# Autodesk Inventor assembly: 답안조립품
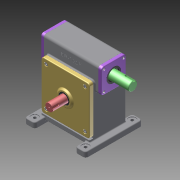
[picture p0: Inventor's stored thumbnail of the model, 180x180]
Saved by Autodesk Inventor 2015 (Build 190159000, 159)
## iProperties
Created: 2025-06
Part Number: 답안조립품
Document SubType Name: Assembly
Designer: User
Author: User
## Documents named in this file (13)
- C:\Users\User\Desktop\750603V1011\답안조립품.iam
- C:\Users\User\Documents\Inventor\6각 구멍붙이 볼트 M6x12.ipt
- C:\Users\User\Desktop\750603V1011\가져온 구성요소\6각 구멍붙이 볼트 M8x20\6각 구멍붙이 볼트 M8x20.ipt
- C:\Users\User\Desktop\750603V1011\가져온 구성요소\깊은 홈 볼 베어링 6206\깊은 홈 볼 베어링 6206.ipt
- C:\Users\User\Desktop\750603V1011\가져온 구성요소\깊은 홈 볼 베어링 6209\깊은 홈 볼 베어링 6209.ipt
- C:\Users\User\Desktop\750603V1011\가져온 구성요소\뒷커버\뒷커버.ipt
- C:\Users\User\Desktop\750603V1011\본체.ipt
- C:\Users\User\Desktop\750603V1011\가져온 구성요소\앞커버\앞커버.ipt
- C:\Users\User\Desktop\750603V1011\가져온 구성요소\오일 실 30 42 7\오일 실 30 42 7.ipt
- C:\Users\User\Desktop\750603V1011\가져온 구성요소\오일 실 35 55 11\오일 실 35 55 11.ipt
- C:\Users\User\Desktop\750603V1011\가져온 구성요소\웜 샤프트\웜 샤프트.ipt
- C:\Users\User\Desktop\750603V1011\가져온 구성요소\웜 휠 커버\웜 휠 커버.ipt
- C:\Users\User\Desktop\750603V1011\가져온 구성요소\웜 휠\웜 휠.ipt
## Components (12 placed, 2 different names)
1. 6각 구멍붙이 볼트 M8x20:1
2. 6각 구멍붙이 볼트 M8x20:2
3. 6각 구멍붙이 볼트 M8x20:3
4. 6각 구멍붙이 볼트 M8x20:4
5. 6각 구멍붙이 볼트 M6x12:1
6. 6각 구멍붙이 볼트 M6x12:3
7. 6각 구멍붙이 볼트 M6x12:4
8. 6각 구멍붙이 볼트 M6x12:5
9. 6각 구멍붙이 볼트 M6x12:2
10. 6각 구멍붙이 볼트 M6x12:6
11. 6각 구멍붙이 볼트 M6x12:7
12. 6각 구멍붙이 볼트 M6x12:8
## Component patterns: 구성요소 패턴 3:2 (2 elements)
